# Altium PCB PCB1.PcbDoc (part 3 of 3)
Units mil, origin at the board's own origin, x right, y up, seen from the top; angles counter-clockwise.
Board outline 5995.03 x 3870.03 mil, 2 copper layers (Top Layer, Bottom Layer); 16 components, 23 nets, 121 pads, 0 vias.
Unrouted connection lines stored in the file: 7.
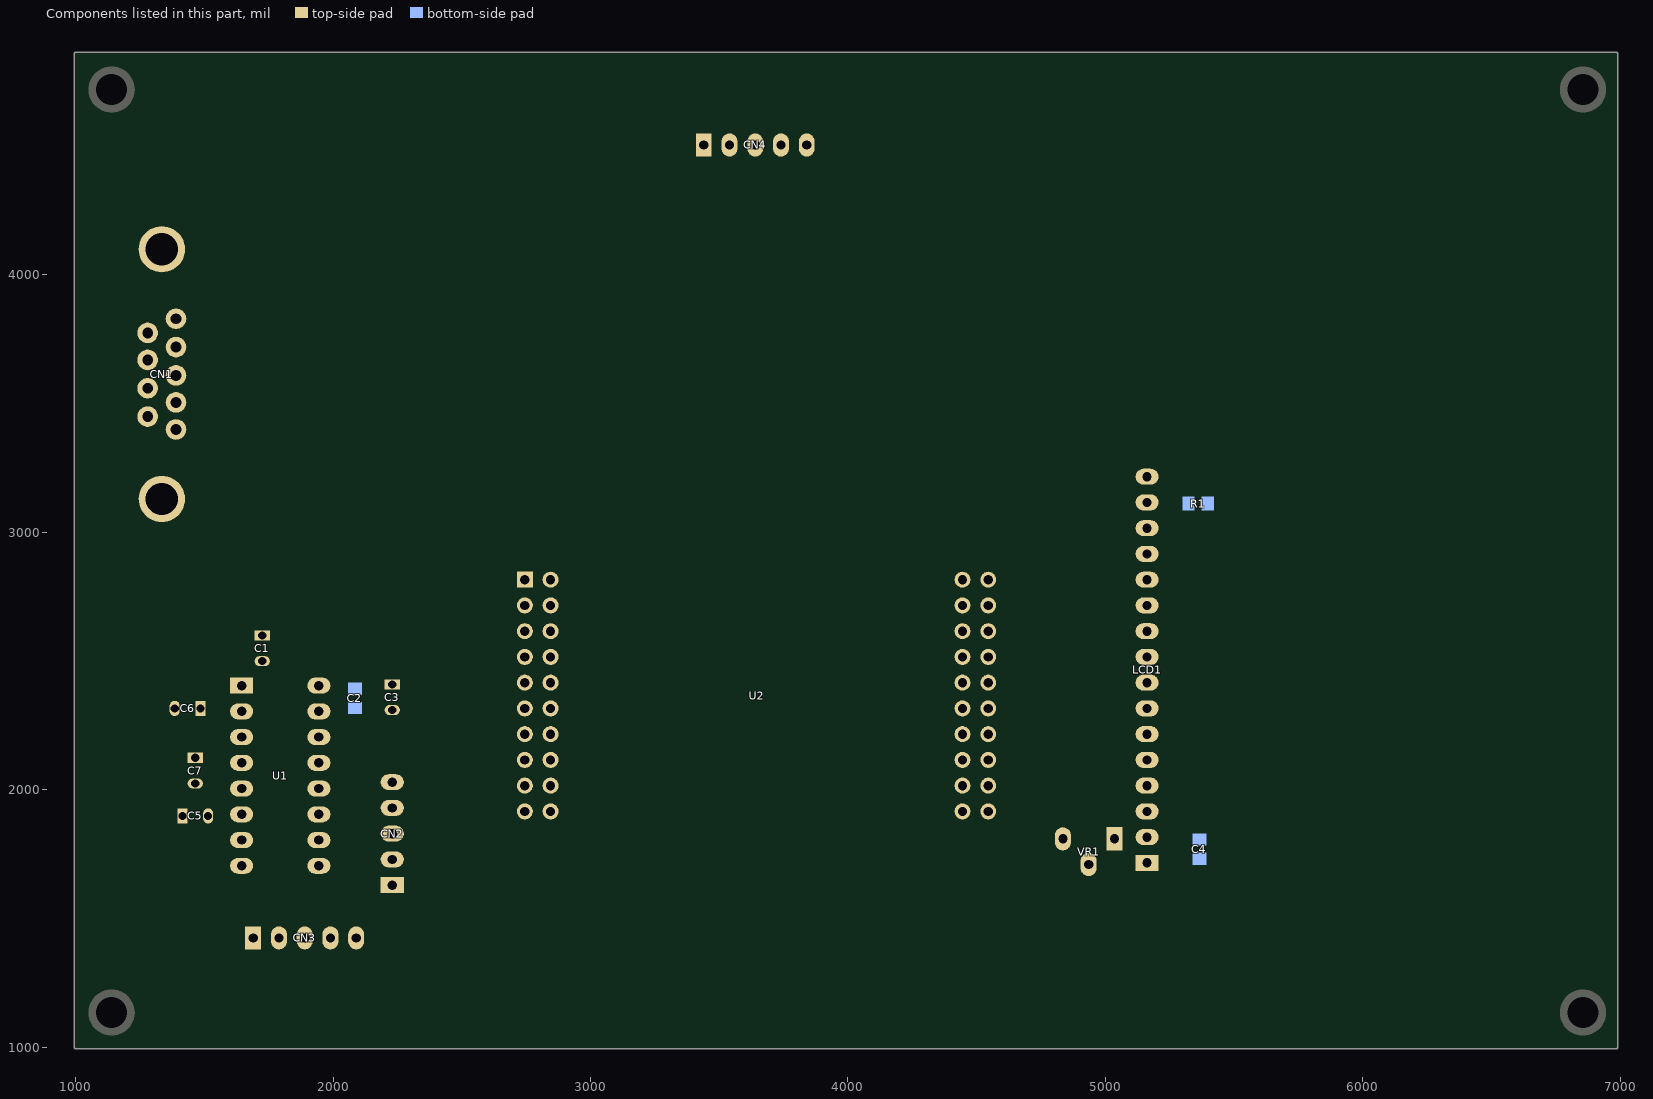
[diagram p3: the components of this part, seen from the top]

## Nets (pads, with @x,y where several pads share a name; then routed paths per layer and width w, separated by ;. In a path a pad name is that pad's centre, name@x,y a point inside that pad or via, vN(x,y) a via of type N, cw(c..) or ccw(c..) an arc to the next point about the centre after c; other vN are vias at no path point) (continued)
copper on no net: (continued)
  Bottom Layer w1: 6729,3794 6729,3823 ; 6729,3857 6729,3909 ; 6730,3319 6730,3386 ; 6730,3416 6730,3434 ; 6730,3464 6730,3482 ; 6730,3512 6730,3527 ; 6730,3605 6730,3620 ; 6730,3651 6730,3662 ; 6730,3704 6730,3720 ; 6730,3750 6730,3760 ; 6730,3794 6730,3824 ; 6730,3858 6730,3909 ; 6731,3319 6731,3386 ; 6731,3416 6731,3434 ; 6731,3464 6731,3482 ; 6731,3513 6731,3528 ; 6731,3605 6731,3620 ; 6731,3651 6731,3662 ; 6731,3704 6731,3720 ; 6731,3751 6731,3760 ; 6731,3794 6731,3824 ; 6731,3858 6731,3909 ; 6732,3319 6732,3387 ; 6732,3416 6732,3434 ; 6732,3465 6732,3482 ; 6732,3513 6732,3528 ; 6732,3605 6732,3620 ; 6732,3651 6732,3662 ; 6732,3704 6732,3720 ; 6732,3751 6732,3760 ; 6732,3795 6732,3824 ; 6732,3859 6732,3909 ; 6733,3319 6733,3360 ; 6733,3362 6733,3367 ; 6733,3370 6733,3371 ; 6733,3378 6733,3388 ; 6733,3417 6733,3434 ; 6733,3465 6733,3482 ; 6733,3513 6733,3528 ; 6733,3559 6733,3560 ; 6733,3604 6733,3621 ; 6733,3651 6733,3663 ; 6733,3704 6733,3721 ; 6733,3751 6733,3760 ; 6733,3795 6733,3825 ; 6733,3859 6733,3909 ; 6734,3319 6734,3360 ; 6734,3363 6734,3367 ; 6734,3370 6734,3374 ; 6734,3376 6734,3388 ; 6734,3417 6734,3435 ; 6734,3465 6734,3483 ; 6734,3513 6734,3528 ; 6734,3559 6734,3561 ; 6734,3604 6734,3621 ; 6734,3652 6734,3663 ; 6734,3704 6734,3721 ; 6734,3751 6734,3760 ; 6734,3795 6734,3825 ; 6734,3860 6734,3909 ; 6735,3319 6735,3360 ; 6735,3363 6735,3366 ; 6735,3370 6735,3374 ; 6735,3376 6735,3389 ; 6735,3417 6735,3435 ; 6735,3465 6735,3483 ; 6735,3514 6735,3529 ; 6735,3559 6735,3562 ; 6735,3604 6735,3621 ; 6735,3652 6735,3663 ; 6735,3704 6735,3721 ; 6735,3752 6735,3760 ; 6735,3795 6735,3826 ; 6735,3861 6735,3909 ; 6736,3319 6736,3360 ; 6736,3361 6736,3362 ; 6736,3363 6736,3366 ; 6736,3370 6736,3374 ; 6736,3376 6736,3390 ; 6736,3417 6736,3435 ; 6736,3466 6736,3483 ; 6736,3514 6736,3529 ; 6736,3559 6736,3563 ; 6736,3603 6736,3621 ; 6736,3652 6736,3663 ; 6736,3703 6736,3721 ; 6736,3752 6736,3760 ; 6736,3795 6736,3826 ; 6736,3861 6736,3909 ; 6737,3319 6737,3360 ; 6737,3361 6737,3362 ; 6737,3364 6737,3366 ; 6737,3367 6737,3368 ; 6737,3370 6737,3374 ; 6737,3376 6737,3392 ; 6737,3418 6737,3435 ; 6737,3466 6737,3483 ; 6737,3514 6737,3529 ; 6737,3560 6737,3564 ; 6737,3603 6737,3622 ; 6737,3652 6737,3664 ; 6737,3703 6737,3722 ; 6737,3752 6737,3760 ; 6737,3795 6737,3827 ; 6737,3862 6737,3909 ; 6738,3319 6738,3360 ; 6738,3361 6738,3363 ; 6738,3364 6738,3365 ; 6738,3367 6738,3368 ; 6738,3370 6738,3374 ; 6738,3376 6738,3393 ; 6738,3418 6738,3436 ; 6738,3466 6738,3484 ; 6738,3514 6738,3529 ; 6738,3560 6738,3566 ; 6738,3602 6738,3622 ; 6738,3653 6738,3664 ; 6738,3702 6738,3722 ; 6738,3752 6738,3760 ; 6738,3795 6738,3827 ; 6738,3862 6738,3909 ; 6739,3319 6739,3360 ; 6739,3361 6739,3363 ; 6739,3366 6739,3368 ; 6739,3370 6739,3374 ; 6739,3376 6739,3395 ; 6739,3418 6739,3436 ; 6739,3466 6739,3484 ; 6739,3515 6739,3530 ; 6739,3560 6739,3567 ; 6739,3601 6739,3622 ; 6739,3653 6739,3664 ; 6739,3700 6739,3722 ; 6739,3753 6739,3760 ; 6739,3795 6739,3827 ; 6739,3863 6739,3909 ; 6740,3319 6740,3360 ; 6740,3361 6740,3363 ; 6740,3366 6740,3368 ; 6740,3370 6740,3374 ; 6740,3376 6740,3397 ; 6740,3418 6740,3436 ; 6740,3467 6740,3484 ; 6740,3515 6740,3530 ; 6740,3560 6740,3569 ; 6740,3599 6740,3622 ; 6740,3653 6740,3664 ; 6740,3698 6740,3722 ; 6740,3753 6740,3760 ; 6740,3795 6740,3828 ; 6740,3863 6740,3909 ; 6741,3319 6741,3360 ; 6741,3361 6741,3364 ; 6741,3366 6741,3368 ; 6741,3370 6741,3374 ; 6741,3376 6741,3401 ; 6741,3419 6741,3436 ; 6741,3467 6741,3484 ; 6741,3515 6741,3530 ; 6741,3561 6741,3571 ; 6741,3597 6741,3623 ; 6741,3653 6741,3665 ; 6741,3695 6741,3723 ; 6741,3753 6741,3760 ; 6741,3795 6741,3828 ; 6741,3864 6741,3909 ; 6742,3319 6742,3574 ; 6742,3595 6742,3674 ; 6742,3686 6742,3909 ; 6743,3319 6743,3579 ; 6743,3590 6743,3909 ; 6744,3319 6744,3909 ; 6745,3319 6745,3909 ; 6746,3319 6746,3909 ; 6747,3319 6747,3909 ; 6748,3319 6748,3909 ; 6749,3319 6749,3909 ; 6750,3319 6750,3909 ; 6751,3319 6751,3909 ; 6752,3319 6752,3909 ; 6753,3319 6753,3909 ; 6754,3319 6754,3909 ; 6755,3319 6755,3909 ; 6756,3319 6756,3909 ; 6757,3319 6757,3909 ; 6758,3319 6758,3909 ; 6759,3319 6759,3909 ; 6760,3319 6760,3909 ; 6761,3319 6761,3909 ; 6762,3319 6762,3909 ; 6763,3319 6763,3909 ; 6764,3319 6764,3909 ; 6765,3319 6765,3360 ; 6765,3362 6765,3367 ; 6765,3370 6765,3371 ; 6765,3378 6765,3725 ; 6765,3729 6765,3816 ; 6765,3820 6765,3909 ; 6766,3319 6766,3360 ; 6766,3363 6766,3367 ; 6766,3370 6766,3374 ; 6766,3375 6766,3416 ; 6766,3420 6766,3521 ; 6766,3525 6766,3622 ; 6766,3626 6766,3725 ; 6766,3729 6766,3799 ; 6766,3803 6766,3816 ; 6766,3820 6766,3909 ; 6767,3319 6767,3360 ; 6767,3363 6767,3366 ; 6767,3370 6767,3374 ; 6767,3375 6767,3416 ; 6767,3420 6767,3457 ; 6767,3469 6767,3521 ; 6767,3525 6767,3568 ; 6767,3578 6767,3622 ; 6767,3626 6767,3725 ; 6767,3729 6767,3734 ; 6767,3746 6767,3799 ; 6767,3803 6767,3816 ; 6767,3820 6767,3843 ; 6767,3850 6767,3859 ; 6767,3865 6767,3909 ; 6768,3319 6768,3360 ; 6768,3361 6768,3362 ; 6768,3364 6768,3366 ; 6768,3370 6768,3374 ; 6768,3375 6768,3416 ; 6768,3420 6768,3457 ; 6768,3469 6768,3521 ; 6768,3525 6768,3565 ; 6768,3578 6768,3622 ; 6768,3626 6768,3683 ; 6768,3685 6768,3725 ; 6768,3729 6768,3734 ; 6768,3746 6768,3799 ; 6768,3803 6768,3816 ; 6768,3820 6768,3843 ; 6768,3850 6768,3858 ; 6768,3865 6768,3909 ; 6769,3319 6769,3360 ; 6769,3361 6769,3362 ; 6769,3364 6769,3365 ; 6769,3367 6769,3368 ; 6769,3370 6769,3374 ; 6769,3375 6769,3457 ; 6769,3469 6769,3564 ; 6769,3578 6769,3683 ; 6769,3687 6769,3725 ; 6769,3729 6769,3734 ; 6769,3746 6769,3816 ; 6769,3820 6769,3843 ; 6769,3850 6769,3858 ; 6769,3865 6769,3909 ; 6770,3319 6770,3360 ; 6770,3361 6770,3363 ; 6770,3367 6770,3368 ; 6770,3370 6770,3374 ; 6770,3375 6770,3464 ; 6770,3469 6770,3563 ; 6770,3570 6770,3574 ; 6770,3578 6770,3683 ; 6770,3687 6770,3725 ; 6770,3729 6770,3742 ; 6770,3746 6770,3816 ; 6770,3820 6770,3843 ; 6770,3851 6770,3858 ; 6770,3865 6770,3909 ; 6771,3319 6771,3360 ; 6771,3361 6771,3363 ; 6771,3366 6771,3368 ; 6771,3370 6771,3374 ; 6771,3375 6771,3464 ; 6771,3469 6771,3563 ; 6771,3568 6771,3574 ; 6771,3578 6771,3683 ; 6771,3687 6771,3725 ; 6771,3729 6771,3742 ; 6771,3746 6771,3816 ; 6771,3820 6771,3843 ; 6771,3851 6771,3857 ; 6771,3865 6771,3909 ; 6772,3319 6772,3360 ; 6772,3361 6772,3364 ; 6772,3366 6772,3368 ; 6772,3370 6772,3374 ; 6772,3375 6772,3385 ; 6772,3388 6772,3390 ; 6772,3393 6772,3401 ; 6772,3408 6772,3416 ; 6772,3420 6772,3425 ; 6772,3433 6772,3442 ; 6772,3450 6772,3464 ; 6772,3469 6772,3486 ; 6772,3492 6772,3493 ; 6772,3497 6772,3502 ; 6772,3506 6772,3508 ; 6772,3514 6772,3521 ; 6772,3525 6772,3530 ; 6772,3538 6772,3547 ; 6772,3554 6772,3562 ; 6772,3567 6772,3574 ; 6772,3578 6772,3593 ; 6772,3601 6772,3606 ; 6772,3614 6772,3622 ; 6772,3626 6772,3633 ; 6772,3639 6772,3641 ; 6772,3645 6772,3653 ; 6772,3660 6772,3667 ; 6772,3670 6772,3672 ; 6772,3675 6772,3680 ; 6772,3690 6772,3692 ; 6772,3699 6772,3710 ; 6772,3717 6772,3725 ; 6772,3729 6772,3742 ; 6772,3746 6772,3761 ; 6772,3765 6772,3766 ; 6772,3772 6772,3782 ; 6772,3788 6772,3790 ; 6772,3793 6772,3799 ; 6772,3803 6772,3807 ; 6772,3812 6772,3816 ; 6772,3820 6772,3827 ; 6772,3836 6772,3843 ; 6772,3851 6772,3857 ; 6772,3865 6772,3909 ; 6773,3319 6773,3385 ; 6773,3389 6773,3390 ; 6773,3393 6773,3400 ; 6773,3409 6773,3416 ; 6773,3420 6773,3425 ; 6773,3434 6773,3441 ; 6773,3451 6773,3464 ; 6773,3469 6773,3485 ; 6773,3497 6773,3502 ; 6773,3515 6773,3521 ; 6773,3525 6773,3530 ; 6773,3539 6773,3546 ; 6773,3556 6773,3562 ; 6773,3567 6773,3574 ; 6773,3578 6773,3593 ; 6773,3602 6773,3607 ; 6773,3615 6773,3622 ; 6773,3626 6773,3632 ; 6773,3645 6773,3651 ; 6773,3662 6773,3667 ; 6773,3671 6773,3672 ; 6773,3675 6773,3680 ; 6773,3690 6773,3692 ; 6773,3701 6773,3709 ; 6773,3718 6773,3725 ; 6773,3729 6773,3742 ; 6773,3746 6773,3761 ; 6773,3773 6773,3781 ; 6773,3793 6773,3799 ; 6773,3803 6773,3808 ; 6773,3813 6773,3816 ; 6773,3820 6773,3826 ; 6773,3837 6773,3843 ; 6773,3847 6773,3848 ; 6773,3852 6773,3857 ; 6773,3865 6773,3909 ; 6774,3319 6774,3385 ; 6774,3393 6774,3399 ; 6774,3410 6774,3416 ; 6774,3420 6774,3425 ; 6774,3435 6774,3440 ; 6774,3451 6774,3464 ; 6774,3469 6774,3484 ; 6774,3497 6774,3502 ; 6774,3516 6774,3521 ; 6774,3525 6774,3531 ; 6774,3540 6774,3545 ; 6774,3556 6774,3562 ; 6774,3566 6774,3574 ; 6774,3578 6774,3593 ; 6774,3603 6774,3607 ; 6774,3616 6774,3622 ; 6774,3626 6774,3632 ; 6774,3645 6774,3651 ; 6774,3663 6774,3667 ; 6774,3675 6774,3680 ; 6774,3690 6774,3692 ; 6774,3702 6774,3708 ; 6774,3719 6774,3725 ; 6774,3729 6774,3742 ; 6774,3746 6774,3761 ; 6774,3774 6774,3780 ; 6774,3793 6774,3799 ; 6774,3803 6774,3809 ; 6774,3813 6774,3816 ; 6774,3820 6774,3826 ; 6774,3837 6774,3843 ; 6774,3847 6774,3848 ; 6774,3852 6774,3856 ; 6774,3860 6774,3861 ; 6774,3865 6774,3909 ; 6775,3319 6775,3385 ; 6775,3393 6775,3399 ; 6775,3402 6775,3407 ; 6775,3411 6775,3416 ; 6775,3420 6775,3431 ; 6775,3435 6775,3440 ; 6775,3444 6775,3449 ; 6775,3451 6775,3457 ; 6775,3469 6775,3484 ; 6775,3488 6775,3492 ; 6775,3497 6775,3502 ; 6775,3508 6775,3511 ; 6775,3516 6775,3521 ; 6775,3525 6775,3536 ; 6775,3540 6775,3545 ; 6775,3548 6775,3553 ; 6775,3557 6775,3561 ; 6775,3566 6775,3574 ; 6775,3578 6775,3599 ; 6775,3603 6775,3612 ; 6775,3617 6775,3622 ; 6775,3626 6775,3631 ; 6775,3636 6775,3639 ; 6775,3645 6775,3650 ; 6775,3655 6775,3659 ; 6775,3664 6775,3667 ; 6775,3675 6775,3683 ; 6775,3687 6775,3697 ; 6775,3702 6775,3707 ; 6775,3711 6775,3716 ; 6775,3720 6775,3725 ; 6775,3729 6775,3735 ; 6775,3746 6775,3761 ; 6775,3766 6775,3770 ; 6775,3775 6775,3780 ; 6775,3784 6775,3788 ; 6775,3793 6775,3799 ; 6775,3803 6775,3810 ; 6775,3814 6775,3816 ; 6775,3820 6775,3825 ; 6775,3829 6775,3835 ; 6775,3837 6775,3843 ; 6775,3847 6775,3848 ; 6775,3852 6775,3856 ; 6775,3860 6775,3861 ; 6775,3865 6775,3909 ; 6776,3319 6776,3388 ; 6776,3393 6776,3398 ; 6776,3402 6776,3408 ; 6776,3411 6776,3416 ; 6776,3420 6776,3431 ; 6776,3435 6776,3439 ; 6776,3443 6776,3457 ; 6776,3469 6776,3484 ; 6776,3488 6776,3492 ; 6776,3497 6776,3502 ; 6776,3507 6776,3512 ; 6776,3517 6776,3521 ; 6776,3525 6776,3536 ; 6776,3540 6776,3544 ; 6776,3548 6776,3554 ; 6776,3557 6776,3561 ; 6776,3566 6776,3574 ; 6776,3578 6776,3599 ; 6776,3603 6776,3612 ; 6776,3617 6776,3622 ; 6776,3626 6776,3631 ; 6776,3635 6776,3640 ; 6776,3645 6776,3649 ; 6776,3654 6776,3660 ; 6776,3664 6776,3671 ; 6776,3675 6776,3683 ; 6776,3687 6776,3698 ; 6776,3703 6776,3707 ; 6776,3711 6776,3716 ; 6776,3720 6776,3725 ; 6776,3729 6776,3735 ; 6776,3746 6776,3761 ; 6776,3765 6776,3771 ; 6776,3775 6776,3780 ; 6776,3784 6776,3789 ; 6776,3793 6776,3799 ; 6776,3803 6776,3810 ; 6776,3815 6776,3816 ; 6776,3820 6776,3825 ; 6776,3829 6776,3843 ; 6776,3847 6776,3849 ; 6776,3852 6776,3856 ; 6776,3859 6776,3861 ; 6776,3865 6776,3909 ; 6777,3319 6777,3389 ; 6777,3393 6777,3398 ; 6777,3402 6777,3408 ; 6777,3412 6777,3416 ; 6777,3420 6777,3430 ; 6777,3435 6777,3439 ; 6777,3443 6777,3457 ; 6777,3469 6777,3484 ; 6777,3488 6777,3493 ; 6777,3497 6777,3502 ; 6777,3507 6777,3513 ; 6777,3517 6777,3521 ; 6777,3525 6777,3535 ; 6777,3540 6777,3544 ; 6777,3548 6777,3554 ; 6777,3558 6777,3561 ; 6777,3566 6777,3574 ; 6777,3578 6777,3598 ; 6777,3603 6777,3613 ; 6777,3617 6777,3622 ; 6777,3626 6777,3631 ; 6777,3635 6777,3640 ; 6777,3645 6777,3649 ; 6777,3653 6777,3660 ; 6777,3664 6777,3671 ; 6777,3675 6777,3683 ; 6777,3687 6777,3699 ; 6777,3703 6777,3707 ; 6777,3710 6777,3717 ; 6777,3720 6777,3725 ; 6777,3729 6777,3735 ; 6777,3746 6777,3761 ; 6777,3765 6777,3771 ; 6777,3775 6777,3780 ; 6777,3784 6777,3789 ; 6777,3793 6777,3799 ; 6777,3803 6777,3811 ; 6777,3820 6777,3825 ; 6777,3829 6777,3843 ; 6777,3847 6777,3849 ; 6777,3853 6777,3855 ; 6777,3859 6777,3861 ; 6777,3865 6777,3909 ; 6778,3319 6778,3389 ; 6778,3393 6778,3398 ; 6778,3412 6778,3416 ; 6778,3420 6778,3427 ; 6778,3435 6778,3439 ; 6778,3450 6778,3464 ; 6778,3469 6778,3484 ; 6778,3487 6778,3493 ; 6778,3497 6778,3502 ; 6778,3506 6778,3513 ; 6778,3517 6778,3521 ; 6778,3525 6778,3532 ; 6778,3540 6778,3544 ; 6778,3558 6778,3561 ; 6778,3566 6778,3574 ; 6778,3578 6778,3595 ; 6778,3603 6778,3613 ; 6778,3617 6778,3622 ; 6778,3626 6778,3631 ; 6778,3635 6778,3641 ; 6778,3645 6778,3649 ; 6778,3653 6778,3660 ; 6778,3664 6778,3671 ; 6778,3675 6778,3683 ; 6778,3687 6778,3699 ; 6778,3703 6778,3707 ; 6778,3720 6778,3725 ; 6778,3729 6778,3742 ; 6778,3746 6778,3761 ; 6778,3765 6778,3771 ; 6778,3775 6778,3780 ; 6778,3784 6778,3789 ; 6778,3793 6778,3799 ; 6778,3803 6778,3812 ; 6778,3820 6778,3825 ; 6778,3836 6778,3843 ; 6778,3847 6778,3849 ; 6778,3853 6778,3855 ; 6778,3859 6778,3861 ; 6778,3865 6778,3909 ; 6779,3319 6779,3389 ; 6779,3393 6779,3398 ; 6779,3412 6779,3416 ; 6779,3420 6779,3425 ; 6779,3434 6779,3439 ; 6779,3451 6779,3464 ; 6779,3469 6779,3484 ; 6779,3487 6779,3493 ; 6779,3497 6779,3502 ; 6779,3506 6779,3513 ; 6779,3517 6779,3521 ; 6779,3525 6779,3531 ; 6779,3539 6779,3544 ; 6779,3558 6779,3562 ; 6779,3566 6779,3574 ; 6779,3578 6779,3593 ; 6779,3602 6779,3613 ; 6779,3617 6779,3622 ; 6779,3626 6779,3631 ; 6779,3635 6779,3641 ; 6779,3645 6779,3649 ; 6779,3653 6779,3660 ; 6779,3664 6779,3671 ; 6779,3675 6779,3683 ; 6779,3687 6779,3699 ; 6779,3703 6779,3707 ; 6779,3720 6779,3725 ; 6779,3729 6779,3742 ; 6779,3746 6779,3761 ; 6779,3765 6779,3771 ; 6779,3775 6779,3780 ; 6779,3784 6779,3789 ; 6779,3793 6779,3799 ; 6779,3803 6779,3812 ; 6779,3820 6779,3825 ; 6779,3837 6779,3843 ; 6779,3847 6779,3850 ; 6779,3853 6779,3855 ; 6779,3859 6779,3861 ; 6779,3865 6779,3909 ; 6780,3319 6780,3389 ; 6780,3393 6780,3398 ; 6780,3412 6780,3416 ; 6780,3420 6780,3425 ; 6780,3431 6780,3439 ; 6780,3443 6780,3447 ; 6780,3452 6780,3464 ; 6780,3469 6780,3484 ; 6780,3487 6780,3493 ; 6780,3497 6780,3502 ; 6780,3506 6780,3513 ; 6780,3517 6780,3521 ; 6780,3525 6780,3530 ; 6780,3537 6780,3544 ; 6780,3558 6780,3562 ; 6780,3567 6780,3574 ; 6780,3578 6780,3593 ; 6780,3600 6780,3613 ; 6780,3617 6780,3622 ; 6780,3626 6780,3631 ; 6780,3635 6780,3641 ; 6780,3645 6780,3649 ; 6780,3653 6780,3660 ; 6780,3664 6780,3672 ; 6780,3675 6780,3683 ; 6780,3687 6780,3699 ; 6780,3703 6780,3707 ; 6780,3720 6780,3725 ; 6780,3729 6780,3742 ; 6780,3746 6780,3761 ; 6780,3765 6780,3771 ; 6780,3775 6780,3780 ; 6780,3784 6780,3789 ; 6780,3793 6780,3799 ; 6780,3803 6780,3811 ; 6780,3820 6780,3825 ; 6780,3829 6780,3833 ; 6780,3838 6780,3843 ; 6780,3847 6780,3850 ; 6780,3854 6780,3855 ; 6780,3858 6780,3861 ; 6780,3865 6780,3909 ; 6781,3319 6781,3389 ; 6781,3393 6781,3408 ; 6781,3412 6781,3416 ; 6781,3420 6781,3425 ; 6781,3429 6781,3439 ; 6781,3443 6781,3448 ; 6781,3452 6781,3464 ; 6781,3469 6781,3484 ; 6781,3487 6781,3493 ; 6781,3497 6781,3502 ; 6781,3507 6781,3512 ; 6781,3517 6781,3521 ; 6781,3525 6781,3530 ; 6781,3534 6781,3554 ; 6781,3558 6781,3562 ; 6781,3567 6781,3574 ; 6781,3578 6781,3593 ; 6781,3597 6781,3613 ; 6781,3617 6781,3622 ; 6781,3626 6781,3631 ; 6781,3635 6781,3641 ; 6781,3645 6781,3649 ; 6781,3653 6781,3660 ; 6781,3664 6781,3672 ; 6781,3675 6781,3683 ; 6781,3687 6781,3699 ; 6781,3703 6781,3717 ; 6781,3720 6781,3725 ; 6781,3729 6781,3742 ; 6781,3746 6781,3761 ; 6781,3765 6781,3771 ; 6781,3775 6781,3780 ; 6781,3784 6781,3789 ; 6781,3793 6781,3799 ; 6781,3803 6781,3810 ; 6781,3815 6781,3816 ; 6781,3820 6781,3825 ; 6781,3829 6781,3834 ; 6781,3838 6781,3843 ; 6781,3847 6781,3850 ; 6781,3858 6781,3861 ; 6781,3865 6781,3909 ; 6782,3319 6782,3389 ; 6782,3393 6782,3407 ; 6782,3411 6782,3416 ; 6782,3420 6782,3424 ; 6782,3429 6782,3439 ; 6782,3443 6782,3449 ; 6782,3452 6782,3464 ; 6782,3469 6782,3484 ; 6782,3487 6782,3493 ; 6782,3497 6782,3502 ; 6782,3507 6782,3512 ; 6782,3517 6782,3521 ; 6782,3525 6782,3530 ; 6782,3534 6782,3553 ; 6782,3557 6782,3563 ; 6782,3569 6782,3574 ; 6782,3578 6782,3593 ; 6782,3597 6782,3612 ; 6782,3617 6782,3622 ; 6782,3626 6782,3631 ; 6782,3635 6782,3641 ; 6782,3645 6782,3649 ; 6782,3654 6782,3660 ; 6782,3664 6782,3672 ; 6782,3675 6782,3683 ; 6782,3687 6782,3698 ; 6782,3703 6782,3716 ; 6782,3720 6782,3725 ; 6782,3729 6782,3742 ; 6782,3746 6782,3761 ; 6782,3766 6782,3770 ; 6782,3775 6782,3780 ; 6782,3784 6782,3789 ; 6782,3793 6782,3799 ; 6782,3803 6782,3809 ; 6782,3814 6782,3816 ; 6782,3820 6782,3825 ; 6782,3829 6782,3834 ; 6782,3838 6782,3843 ; 6782,3847 6782,3851 ; 6782,3858 6782,3861 ; 6782,3865 6782,3909 ; 6783,3319 6783,3389 ; 6783,3393 6783,3399 ; 6783,3400 6783,3406 ; 6783,3411 6783,3416 ; 6783,3420 6783,3425 ; 6783,3429 6783,3439 ; 6783,3444 6783,3448 ; 6783,3452 6783,3464 ; 6783,3469 6783,3484 ; 6783,3487 6783,3493 ; 6783,3497 6783,3502 ; 6783,3508 6783,3511 ; 6783,3516 6783,3521 ; 6783,3525 6783,3530 ; 6783,3534 6783,3545 ; 6783,3546 6783,3552 ; 6783,3557 6783,3563 ; 6783,3571 6783,3574 ; 6783,3578 6783,3593 ; 6783,3597 6783,3611 ; 6783,3617 6783,3622 ; 6783,3626 6783,3631 ; 6783,3635 6783,3641 ; 6783,3645 6783,3650 ; 6783,3655 6783,3659 ; 6783,3664 6783,3672 ; 6783,3675 6783,3682 ; 6783,3687 6783,3697 ; 6783,3702 6783,3708 ; 6783,3709 6783,3715 ; 6783,3720 6783,3725 ; 6783,3729 6783,3742 ; 6783,3746 6783,3761 ; 6783,3767 6783,3769 ; 6783,3775 6783,3780 ; 6783,3784 6783,3789 ; 6783,3793 6783,3799 ; 6783,3803 6783,3809 ; 6783,3813 6783,3816 ; 6783,3820 6783,3825 ; 6783,3830 6783,3834 ; 6783,3838 6783,3843 ; 6783,3847 6783,3851 ; 6783,3857 6783,3861 ; 6783,3865 6783,3909 ; 6784,3319 6784,3389 ; 6784,3393 6784,3399 ; 6784,3410 6784,3416 ; 6784,3420 6784,3425 ; 6784,3435 6784,3439 ; 6784,3452 6784,3457 ; 6784,3469 6784,3484 ; 6784,3487 6784,3493 ; 6784,3497 6784,3502 ; 6784,3516 6784,3521 ; 6784,3525 6784,3530 ; 6784,3540 6784,3545 ; 6784,3556 6784,3564 ; 6784,3578 6784,3593 ; 6784,3603 6784,3606 ; 6784,3616 6784,3622 ; 6784,3626 6784,3631 ; 6784,3635 6784,3641 ; 6784,3645 6784,3651 ; 6784,3663 6784,3672 ; 6784,3675 6784,3679 ; 6784,3687 6784,3692 ; 6784,3702 6784,3708 ; 6784,3719 6784,3725 ; 6784,3729 6784,3734 ; 6784,3746 6784,3761 ; 6784,3774 6784,3780 ; 6784,3784 6784,3789 ; 6784,3793 6784,3799 ; 6784,3803 6784,3808 ; 6784,3813 6784,3816 ; 6784,3820 6784,3825 ; 6784,3838 6784,3843 ; 6784,3847 6784,3851 ; 6784,3857 6784,3861 ; 6784,3865 6784,3909 ; 6785,3319 6785,3389 ; 6785,3393 6785,3399 ; 6785,3409 6785,3416 ; 6785,3420 6785,3426 ; 6785,3435 6785,3439 ; 6785,3452 6785,3457 ; 6785,3469 6785,3484 ; 6785,3487 6785,3493 ; 6785,3497 6785,3502 ; 6785,3506 6785,3507 ; 6785,3515 6785,3521 ; 6785,3525 6785,3531 ; 6785,3540 6785,3545 ; 6785,3555 6785,3566 ; 6785,3578 6785,3594 ; 6785,3603 6785,3606 ; 6785,3615 6785,3622 ; 6785,3626 6785,3631 ; 6785,3635 6785,3641 ; 6785,3645 6785,3651 ; 6785,3662 6785,3672 ; 6785,3675 6785,3679 ; 6785,3686 6785,3692 ; 6785,3701 6785,3708 ; 6785,3718 6785,3725 ; 6785,3729 6785,3734 ; 6785,3746 6785,3761 ; 6785,3773 6785,3780 ; 6785,3784 6785,3789 ; 6785,3793 6785,3799 ; 6785,3803 6785,3807 ; 6785,3812 6785,3816 ; 6785,3820 6785,3825 ; 6785,3837 6785,3843 ; 6785,3847 6785,3852 ; 6785,3857 6785,3861 ; 6785,3865 6785,3909 ; 6786,3319 6786,3389 ; 6786,3393 6786,3400 ; 6786,3408 6786,3416 ; 6786,3420 6786,3427 ; 6786,3435 6786,3439 ; 6786,3443 6786,3444 ; 6786,3450 6786,3457 ; 6786,3469 6786,3484 ; 6786,3487 6786,3493 ; 6786,3497 6786,3502 ; 6786,3506 6786,3509 ; 6786,3513 6786,3521 ; 6786,3525 6786,3532 ; 6786,3540 6786,3546 ; 6786,3554 6786,3568 ; 6786,3578 6786,3595 ; 6786,3603 6786,3606 ; 6786,3613 6786,3622 ; 6786,3626 6786,3631 ; 6786,3635 6786,3641 ; 6786,3645 6786,3653 ; 6786,3660 6786,3672 ; 6786,3675 6786,3679 ; 6786,3685 6786,3692 ; 6786,3699 6786,3708 ; 6786,3716 6786,3725 ; 6786,3729 6786,3734 ; 6786,3746 6786,3761 ; 6786,3765 6786,3767 ; 6786,3772 6786,3780 ; 6786,3784 6786,3789 ; 6786,3793 6786,3799 ; 6786,3803 6786,3806 ; 6786,3811 6786,3816 ; 6786,3820 6786,3825 ; 6786,3828 6786,3830 ; 6786,3836 6786,3843 ; 6786,3847 6786,3852 ; 6786,3856 6786,3861 ; 6786,3865 6786,3909 ; 6787,3319 6787,3503 ; 6787,3507 6787,3761 ; 6787,3765 6787,3909 ; 6788,3319 6788,3503 ; 6788,3507 6788,3761 ; 6788,3766 6788,3909 ; 6789,3319 6789,3503 ; 6789,3508 6789,3513 ; 6789,3515 6789,3762 ; 6789,3767 6789,3772 ; 6789,3774 6789,3909 ; 6790,3319 6790,3504 ; 6790,3515 6790,3762 ; 6790,3774 6790,3909 ; 6791,3319 6791,3505 ; 6791,3515 6791,3763 ; 6791,3774 6791,3909 ; 6792,3319 6792,3506 ; 6792,3514 6792,3764 ; 6792,3773 6792,3909 ; 6793,3319 6793,3909 ; 6794,3319 6794,3909 ; 6795,3319 6795,3909 ; 6796,3319 6796,3909 ; 6797,3319 6797,3909 ; 6798,3319 6798,3909 ; 6799,3319 6799,3909 ; 6800,3319 6800,3909 ; 6801,3319 6801,3909 ; 6802,3319 6802,3909 ; 6803,3319 6803,3909 ; 6804,3319 6804,3909 ; 6805,3319 6805,3909 ; 6806,3319 6806,3909 ; 6807,3320 6807,3909 ; 6808,3320 6808,3909 ; 6809,3320 6809,3909 ; 6810,3321 6810,3909 ; 6811,3321 6811,3909 ; 6812,3321 6812,3909 ; 6813,3322 6813,3909 ; 6814,3322 6814,3909 ; 6815,3323 6815,3909 ; 6816,3323 6816,3909 ; 6817,3324 6817,3909 ; 6818,3325 6818,3909 ; 6819,3325 6819,3909 ; 6820,3326 6820,3909 ; 6821,3327 6821,3909 ; 6822,3328 6822,3909 ; 6823,3329 6823,3909 ; 6824,3330 6824,3909 ; 6825,3331 6825,3909 ; 6826,3332 6826,3909 ; 6827,3333 6827,3909 ; 6828,3334 6828,3909 ; 6829,3335 6829,3909 ; 6830,3337 6830,3909 ; 6831,3338 6831,3909 ; 6832,3340 6832,3909 ; 6833,3342 6833,3909 ; 6834,3344 6834,3909

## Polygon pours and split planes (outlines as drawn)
GND on Bottom Layer "GND_L02_P008" (solid, remove dead copper, pour order 8): 1000,4860 1000,1000 6985,1000 6985,4860

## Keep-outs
Keep-Out Layer:
  lines w10: 1000,1000 1000,4860 6985,4860 6985,1000 1000,1000

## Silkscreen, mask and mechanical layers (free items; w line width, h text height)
Top Overlay:
  text "GND" at 2325,2000 h50
  text "GND" at 2330,1905 h50
  text "GND" at 2340,1805 h50
  text "R1OUT" at 2340,1705 h50
  text "T1IN" at 2335,1590 h50
  text "T1OUT" at 1710,1085 h50 r90
  text "R1IN" at 1815,1085 h50 r90
  text "GND" at 1915,1085 h50 r90
  text "GND" at 2030,1085 h50 r90
  text "GND" at 2150,1085 h50 r90

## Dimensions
665,1520 to 640,1330 on Top Overlay
1140,1520 to 1190,2120 on Top Overlay
1455,1135 to 1445,1330 on Top Overlay
1140,555 to 2330,1450 on Top Overlay
7505,4720 to 7500,4346.5 on Top Overlay
6855,5250 to 6277.01,5210 on Top Overlay
6277.01,4620 to 5317.01,4660 on Top Overlay
6760,1616.5 to 6750,4346.5 on Top Overlay
6855,1135 to 6855,4720 on Top Overlay
1140,4720 to 6855,4720 on Top Overlay
865,1000 to 665,4860 on Top Overlay
1000,950 to 6985,870 on Top Overlay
